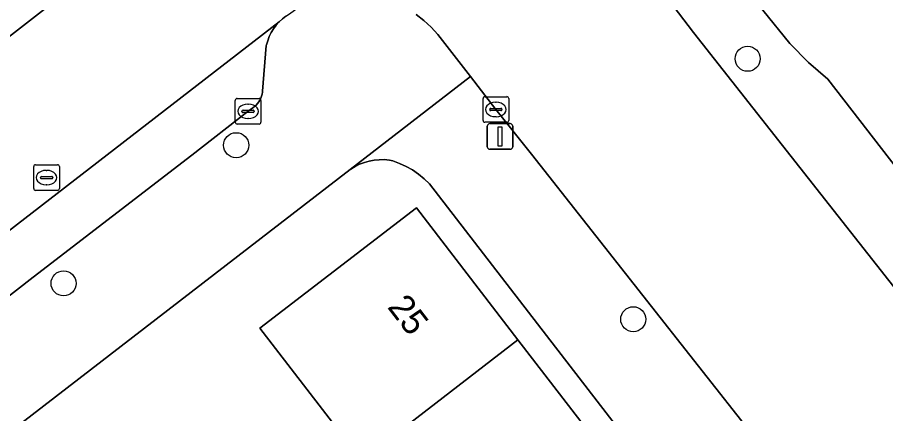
# Model space of a CAD drawing. Extents: x 159217 to 160349, y 381246 to 382172.
# Drawn here: x 159691.38 to 159725.23, y 381553.5 to 381568.95 of the extents above; entities that cross this region are included whole.
import ezdxf

# ---------------------------------------------------------------- set-up
doc = ezdxf.new("R2010")
doc.units = 0
for name, color, linetype in [('IMGEO_Boom', 7, 'Continuous'), ('IMGEO_Erf', 7, 'Continuous'), ('IMGEO_Kolk', 7, 'Continuous'), ('IMGEO_Lichtmast', 7, 'Continuous'), ('IMGEO_Pand', 7, 'Continuous'), ('IMGEO_Pand_nummerreeks', 7, 'Continuous'), ('IMGEO_Parkeervlak_gesloten', 7, 'Continuous'), ('IMGEO_Parkeervlak_open', 7, 'Continuous'), ('IMGEO_Rijbaan_lokaal_gesloten', 7, 'Continuous'), ('IMGEO_Rioolput', 7, 'Continuous'), ('IMGEO_Voetpad_open', 7, 'Continuous')]:
    doc.layers.add(name, color=color, linetype=linetype)

msp = doc.modelspace()

# ---------------------------------------------------------------- linework, layer by layer
at = {"layer": 'IMGEO_Boom'}
for centre in [(159719.85, 381567.338), (159699.911, 381563.967), (159693.182, 381558.578), (159715.39, 381557.179)]:
    msp.add_circle(centre, 0.489, dxfattribs=at)
at = {"layer": 'IMGEO_Erf'}
for points in [[(159719.386, 381570.545), (159721.497, 381567.938), (159722.219, 381567.199), (159722.971, 381566.548), (159732.689, 381554.002)], [(159727.181, 381536.865), (159707.443, 381562.46), (159707.241, 381562.66), (159707.022, 381562.841), (159706.788, 381563.002), (159706.541, 381563.142), (159706.282, 381563.259), (159706.013, 381563.352), (159705.882, 381563.388), (159705.685, 381563.404), (159705.488, 381563.402), (159705.291, 381563.383), (159705.097, 381563.346), (159704.907, 381563.292), (159704.722, 381563.222), (159704.545, 381563.135), (159704.376, 381563.032), (159704.352, 381563.016), (159691.497, 381553.096)], [(159727.061, 381524.467), (159723.113, 381529.596), (159724.651, 381530.79), (159722.649, 381533.39), (159720.285, 381531.57), (159716.351, 381536.679), (159712.5, 381541.681), (159708.656, 381546.673), (159704.8, 381551.682), (159703.888, 381552.866), (159700.838, 381556.828), (159706.936, 381561.522), (159710.897, 381556.378), (159714.753, 381551.369), (159718.598, 381546.376), (159722.448, 381541.375), (159726.383, 381536.264)]]:
    msp.add_lwpolyline(points, dxfattribs=at)
at = {"layer": 'IMGEO_Kolk'}
for p, q in [((159699.875, 381564.864), (159699.875, 381565.716)), ((159699.95, 381565.79), (159700.802, 381565.79)), ((159700.876, 381565.716), (159700.876, 381564.864)), ((159709.534, 381564.934), (159709.534, 381565.786)), ((159709.609, 381565.86), (159710.461, 381565.86)), ((159710.022, 381565.64), (159710.047, 381565.64)), ((159710.535, 381565.786), (159710.535, 381564.934)), ((159700.177, 381565.333), (159700.575, 381565.333)), ((159700.363, 381565.57), (159700.388, 381565.57)), ((159709.793, 381565.354), (159709.793, 381565.366)), ((159710.231, 381565.317), (159709.833, 381565.317)), ((159709.836, 381565.403), (159710.234, 381565.403)), ((159710.277, 381565.366), (159710.277, 381565.354)), ((159700.134, 381565.284), (159700.134, 381565.296)), ((159700.572, 381565.247), (159700.174, 381565.247)), ((159700.386, 381565.01), (159700.361, 381565.01)), ((159700.618, 381565.296), (159700.618, 381565.284)), ((159710.045, 381565.08), (159710.02, 381565.08)), ((159700.802, 381564.79), (159699.95, 381564.79)), ((159710.461, 381564.86), (159709.609, 381564.86))]:
    msp.add_line(p, q, dxfattribs=at)
for points in [[(159699.875, 381564.864), (159699.875, 381565.716)], [(159699.95, 381565.79), (159700.802, 381565.79)], [(159700.876, 381565.716), (159700.876, 381564.864)], [(159709.534, 381564.934), (159709.534, 381565.786)], [(159709.609, 381565.86), (159710.461, 381565.86)], [(159710.535, 381565.786), (159710.535, 381564.934)], [(159700.802, 381564.79), (159699.95, 381564.79)], [(159710.461, 381564.86), (159709.609, 381564.86)]]:
    msp.add_lwpolyline(points, dxfattribs=at)
for centre, radius, start, end in [((159699.952, 381565.714), 0.0765, 91.552, 178.448), ((159699.952, 381565.714), 0.0765, 91.552, 178.448), ((159700.8, 381565.714), 0.0765, 1.552, 88.448), ((159700.8, 381565.714), 0.0765, 1.552, 88.448), ((159709.611, 381565.784), 0.0765, 91.552, 178.448), ((159709.611, 381565.784), 0.0765, 91.552, 178.448), ((159710.459, 381565.784), 0.0765, 1.552, 88.448), ((159710.459, 381565.784), 0.0765, 1.552, 88.448), ((159700.174, 381565.293), 0.0403, 85.8775, 175.7526), ((159700.579, 381565.295), 0.0386, 1.7309, 96.639), ((159709.833, 381565.363), 0.0403, 85.8775, 175.7526), ((159709.83, 381565.353), 0.0366, 178.938, 274.7102), ((159710.234, 381565.36), 0.043, 264.8664, 352.4533), ((159710.238, 381565.365), 0.0386, 1.7309, 96.639), ((159700.171, 381565.283), 0.0366, 178.938, 274.7102), ((159700.575, 381565.29), 0.043, 264.8664, 352.4533), ((159699.952, 381564.866), 0.0765, 181.552, 268.448), ((159699.952, 381564.866), 0.0765, 181.552, 268.448), ((159700.8, 381564.866), 0.0765, 271.552, 358.448), ((159700.8, 381564.866), 0.0765, 271.552, 358.448), ((159709.611, 381564.936), 0.0765, 181.552, 268.448), ((159709.611, 381564.936), 0.0765, 181.552, 268.448), ((159710.459, 381564.936), 0.0765, 271.552, 358.448), ((159710.459, 381564.936), 0.0765, 271.552, 358.448)]:
    msp.add_arc(centre, radius, start, end, dxfattribs=at)
for centre, major_axis, ratio, start_param, end_param in [((159710.021, 381565.36), (-0.387, 0.002), 0.722429, 4.712389, 7.853982), ((159710.046, 381565.36), (-0.39, 0.002), 0.717154, 1.570796, 4.712389), ((159700.362, 381565.29), (-0.387, 0.002), 0.722429, 4.712389, 7.853982), ((159700.387, 381565.29), (-0.39, 0.002), 0.717154, 1.570796, 4.712389)]:
    msp.add_ellipse(centre, major_axis=major_axis, ratio=ratio, start_param=start_param, end_param=end_param, dxfattribs=at)
at = {"layer": 'IMGEO_Lichtmast'}
for p, q in [((159709.7, 381563.908), (159709.7, 381564.708)), ((159709.7, 381564.708), (159709.7, 381563.908)), ((159709.8, 381564.808), (159710.59, 381564.808)), ((159710.59, 381564.808), (159709.8, 381564.808)), ((159710.69, 381564.708), (159710.69, 381563.908)), ((159710.69, 381563.908), (159710.69, 381564.708)), ((159710.59, 381563.808), (159709.8, 381563.808)), ((159709.8, 381563.808), (159710.59, 381563.808))]:
    msp.add_line(p, q, dxfattribs=at)
msp.add_lwpolyline([(159710.12, 381564.683), (159710.27, 381564.683), (159710.27, 381563.933), (159710.12, 381563.933), (159710.12, 381564.683)], dxfattribs=at)
for centre, start, end in [((159709.8, 381564.708), 90, 180), ((159709.8, 381564.708), 90, 180), ((159710.59, 381564.708), 0, 90), ((159710.59, 381564.708), 360, 90), ((159709.8, 381563.908), 180, 270), ((159709.8, 381563.908), 180, 270), ((159710.59, 381563.908), 270, 0), ((159710.59, 381563.908), 270, 0)]:
    msp.add_arc(centre, 0.1, start, end, dxfattribs=at)
at = {"layer": 'IMGEO_Pand'}
for points in [[(159704.8, 381551.682), (159706.662, 381553.116), (159710.897, 381556.378), (159706.936, 381561.522), (159700.838, 381556.828), (159703.888, 381552.866)], [(159714.753, 381551.369), (159710.897, 381556.378), (159706.662, 381553.116), (159704.8, 381551.682), (159708.656, 381546.673), (159710.712, 381548.257)]]:
    msp.add_lwpolyline(points, close=True, dxfattribs=at)
at = {"layer": 'IMGEO_Parkeervlak_gesloten'}
msp.add_lwpolyline([(159689.149, 381556.615), (159691.999, 381558.814), (159698.177, 381563.581), (159700.375, 381565.291), (159700.566, 381565.427), (159700.63, 381565.477), (159700.688, 381565.533), (159700.742, 381565.594), (159700.79, 381565.659), (159700.832, 381565.728), (159700.868, 381565.801), (159700.897, 381565.877), (159700.919, 381565.955), (159700.934, 381566.034), (159700.939, 381566.078), (159701.086, 381567.854), (159701.091, 381567.876), (159701.139, 381568.042), (159701.201, 381568.204), (159701.278, 381568.359), (159701.368, 381568.507), (159701.471, 381568.646), (159701.586, 381568.776), (159669.88, 381544.26)], dxfattribs=at)
at = {"layer": 'IMGEO_Parkeervlak_open'}
for points in [[(159691.497, 381553.096), (159704.352, 381563.016), (159709.042, 381566.641), (159707.766, 381568.286), (159707.511, 381568.572), (159707.231, 381568.834), (159706.929, 381569.07)], [(159701.848, 381569.002), (159701.712, 381568.895), (159701.586, 381568.776), (159701.471, 381568.646), (159701.368, 381568.507), (159701.278, 381568.359), (159701.201, 381568.204), (159701.139, 381568.042), (159701.091, 381567.876), (159701.086, 381567.854), (159700.939, 381566.078), (159700.934, 381566.034), (159700.919, 381565.955), (159700.897, 381565.877), (159700.868, 381565.801), (159700.832, 381565.728), (159700.79, 381565.659), (159700.742, 381565.594), (159700.688, 381565.533), (159700.63, 381565.477), (159700.566, 381565.427), (159700.375, 381565.291), (159698.177, 381563.581), (159691.999, 381558.814), (159689.149, 381556.615)]]:
    msp.add_lwpolyline(points, dxfattribs=at)
at = {"layer": 'IMGEO_Rijbaan_lokaal_gesloten'}
for points in [[(159669.88, 381544.26), (159701.586, 381568.776), (159701.712, 381568.895), (159701.848, 381569.002), (159701.993, 381569.096), (159715.403, 381578.982), (159715.427, 381579.011), (159715.559, 381579.15), (159715.703, 381579.276), (159715.857, 381579.39), (159715.962, 381579.454), (159740.465, 381608.25)], [(159724.124, 381598.501), (159722.315, 381596.319), (159720.068, 381593.859), (159713.929, 381587.582), (159708.867, 381582.687), (159703.645, 381578.06), (159697.824, 381573.473), (159689.155, 381566.722), (159677.732, 381557.93), (159669.544, 381551.57), (159667.146, 381549.71), (159654.468, 381539.832)], [(159728.347, 381554.892), (159717.739, 381568.362), (159716.782, 381569.632)], [(159706.929, 381569.07), (159707.231, 381568.834), (159707.511, 381568.572), (159707.766, 381568.286), (159709.042, 381566.641), (159710.036, 381565.36), (159711.418, 381563.617), (159720.102, 381552.591)]]:
    msp.add_lwpolyline(points, dxfattribs=at)
at = {"layer": 'IMGEO_Rioolput'}
for p, q in [((159692.018, 381562.279), (159692.018, 381563.131)), ((159692.093, 381563.205), (159692.945, 381563.205)), ((159692.506, 381562.985), (159692.531, 381562.985)), ((159693.019, 381563.131), (159693.019, 381562.279)), ((159692.277, 381562.699), (159692.277, 381562.711)), ((159692.715, 381562.662), (159692.317, 381562.662)), ((159692.32, 381562.748), (159692.718, 381562.748)), ((159692.761, 381562.711), (159692.761, 381562.699)), ((159692.529, 381562.425), (159692.504, 381562.425)), ((159692.945, 381562.205), (159692.093, 381562.205))]:
    msp.add_line(p, q, dxfattribs=at)
for points in [[(159692.018, 381562.279), (159692.018, 381563.131)], [(159692.093, 381563.205), (159692.945, 381563.205)], [(159693.019, 381563.131), (159693.019, 381562.279)], [(159692.945, 381562.205), (159692.093, 381562.205)]]:
    msp.add_lwpolyline(points, dxfattribs=at)
for centre, radius, start, end in [((159692.095, 381563.129), 0.0765, 91.552, 178.448), ((159692.095, 381563.129), 0.0765, 91.552, 178.448), ((159692.943, 381563.129), 0.0765, 1.552, 88.448), ((159692.943, 381563.129), 0.0765, 1.552, 88.448), ((159692.317, 381562.708), 0.0403, 85.8775, 175.7526), ((159692.314, 381562.698), 0.0366, 178.938, 274.7102), ((159692.718, 381562.705), 0.043, 264.8664, 352.4533), ((159692.722, 381562.71), 0.0386, 1.7309, 96.639), ((159692.095, 381562.281), 0.0765, 181.552, 268.448), ((159692.095, 381562.281), 0.0765, 181.552, 268.448), ((159692.943, 381562.281), 0.0765, 271.552, 358.448), ((159692.943, 381562.281), 0.0765, 271.552, 358.448)]:
    msp.add_arc(centre, radius, start, end, dxfattribs=at)
for centre, major_axis, ratio, start_param, end_param in [((159692.505, 381562.705), (-0.387, 0.002), 0.722429, 4.712389, 7.853982), ((159692.53, 381562.705), (-0.39, 0.002), 0.717154, 1.570796, 4.712389)]:
    msp.add_ellipse(centre, major_axis=major_axis, ratio=ratio, start_param=start_param, end_param=end_param, dxfattribs=at)
at = {"layer": 'IMGEO_Voetpad_open'}
for points in [[(159689.155, 381566.722), (159697.824, 381573.473), (159703.645, 381578.06), (159708.867, 381582.687)], [(159732.689, 381554.002), (159722.971, 381566.548), (159722.219, 381567.199), (159721.497, 381567.938), (159719.386, 381570.545)], [(159716.782, 381569.632), (159717.739, 381568.362), (159728.347, 381554.892)], [(159728.968, 381541.067), (159720.102, 381552.591), (159711.418, 381563.617), (159710.036, 381565.36), (159709.042, 381566.641), (159704.352, 381563.016), (159704.376, 381563.032), (159704.545, 381563.135), (159704.722, 381563.222), (159704.907, 381563.292), (159705.097, 381563.346), (159705.291, 381563.383), (159705.488, 381563.402), (159705.685, 381563.404), (159705.882, 381563.388), (159706.013, 381563.352), (159706.282, 381563.259), (159706.541, 381563.142), (159706.788, 381563.002), (159707.022, 381562.841), (159707.241, 381562.66), (159707.443, 381562.46), (159727.181, 381536.865)]]:
    msp.add_lwpolyline(points, dxfattribs=at)

# ---------------------------------------------------------------- texts
at = {"layer": 'IMGEO_Pand_nummerreeks'}
msp.add_text('25', height=1, rotation=307.5939, dxfattribs=at).set_placement((159705.778, 381557.649))

doc.saveas('drawing.dxf')
